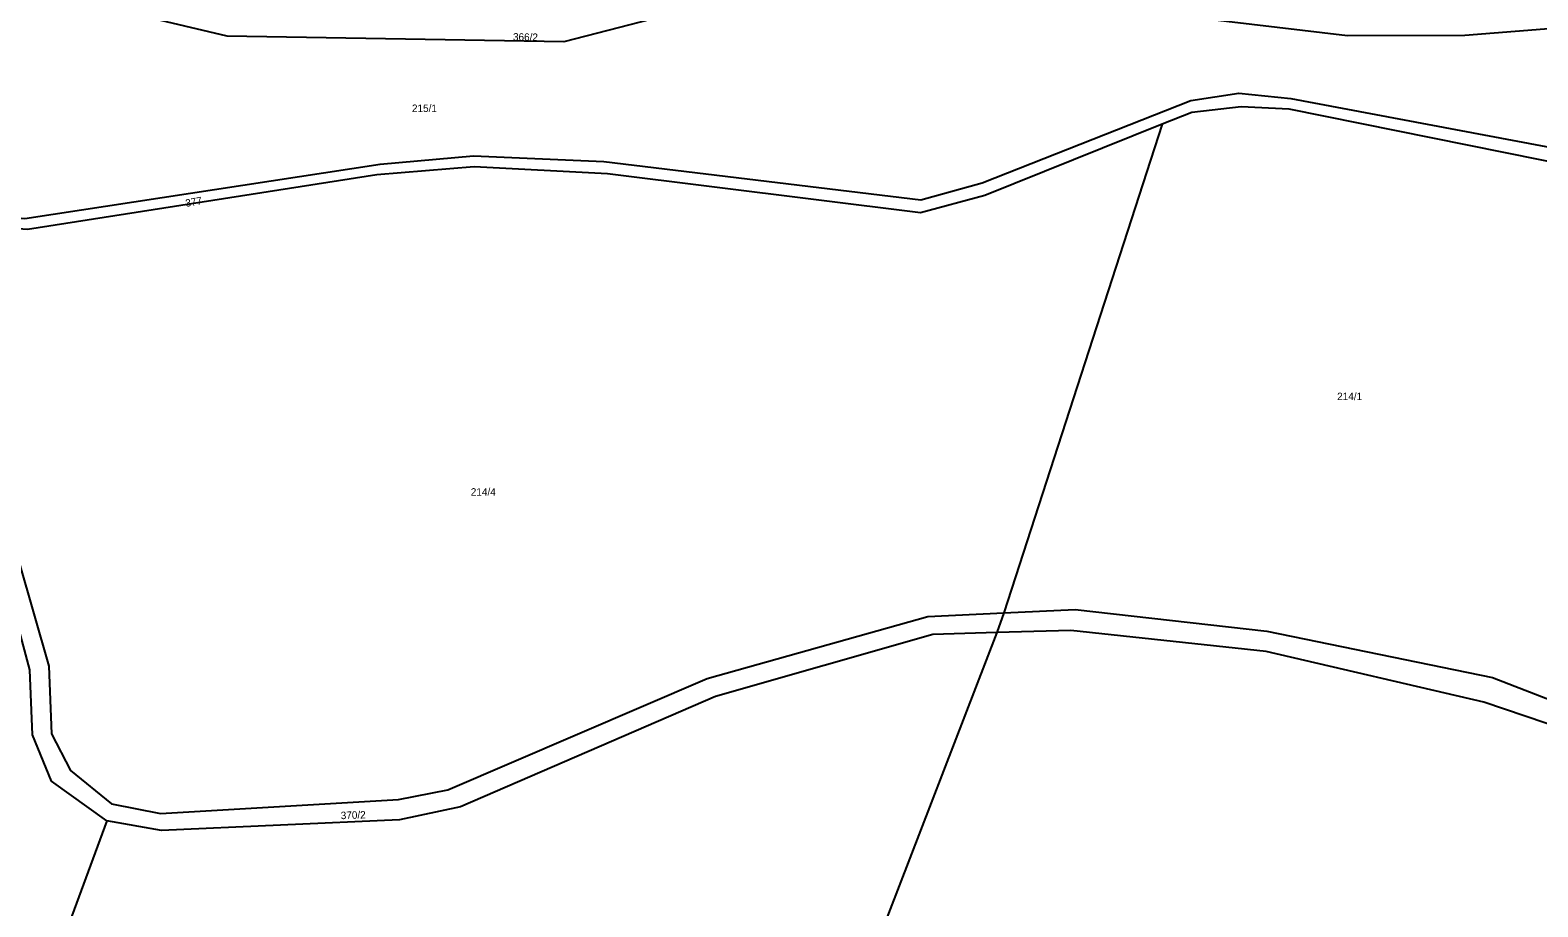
# Model space of a CAD drawing. Extents: x -880531 to -877616, y -1023932 to -1021350.
# Drawn here: x -878520.6 to -878177.4, y -1022709.3 to -1022509.8 of the extents above; entities that cross this region are included whole.
import ezdxf

# ---------------------------------------------------------------- set-up
doc = ezdxf.new("R2010")
doc.units = 0
doc.layers.add('Hranice parcel', color=7, linetype='Continuous')
doc.layers.add('Parcelní čísla', color=7, linetype='Continuous')

msp = doc.modelspace()

# ---------------------------------------------------------------- linework, layer by layer
at = {"layer": 'Hranice parcel'}
for p, q in [((-878262.91, -1022531.2), (-878298.99, -1022642.4)), ((-878298.99, -1022642.4), (-878300.59, -1022646.88)), ((-878300.59, -1022646.88), (-878347.85, -1022769.53)), ((-878503.14, -1022689.72), (-878513.6, -1022718.13))]:
    msp.add_line(p, q, dxfattribs=at)
for points in [[(-878125.35, -1022504.99), (-878146.35, -1022507.21), (-878194.02, -1022510.96), (-878220.76, -1022511.05), (-878280.27, -1022503.97), (-878335.4, -1022493.58), (-878344.86, -1022493.55), (-878371.73, -1022505.4), (-878399.1, -1022512.43), (-878475.7, -1022511.16), (-878508.77, -1022503.35), (-878545.47, -1022484.68), (-878615.6, -1022481.24), (-878635.5, -1022474.3), (-878648.14, -1022478.45), (-878668.08, -1022496.96), (-878691.68, -1022527.88), (-878708.19, -1022539.68), (-878731.2, -1022543.61), (-878748.07, -1022535.1), (-878763.51, -1022523.14)], [(-878772.34, -1022525.45), (-878758.55, -1022537.32), (-878734.74, -1022552.47), (-878725.11, -1022552.52), (-878697.59, -1022542.6), (-878692.56, -1022542.42), (-878672.91, -1022533.58), (-878660.33, -1022531.18), (-878648.04, -1022531.76), (-878616.24, -1022536.33), (-878607.61, -1022539.29), (-878559.76, -1022547.29), (-878533.18, -1022551.67), (-878521.77, -1022552.65), (-878440.9, -1022540.29), (-878419.64, -1022538.34), (-878389.99, -1022539.7), (-878317.85, -1022548.39), (-878303.92, -1022544.55), (-878256.37, -1022525.75), (-878245.48, -1022524.13), (-878233.68, -1022525.33), (-878151.01, -1022540.9)], [(-878152.5, -1022544.22), (-878234.05, -1022527.78), (-878244.93, -1022527.2), (-878256.18, -1022528.49), (-878262.91, -1022531.2)], [(-878262.91, -1022531.2), (-878303.25, -1022547.39), (-878317.9, -1022551.31), (-878389.14, -1022542.46), (-878419.52, -1022540.9), (-878441.69, -1022542.71), (-878521.19, -1022555.14), (-878532.17, -1022554.36), (-878559.74, -1022550.55), (-878604.26, -1022543.95)], [(-878604.26, -1022543.95), (-878579.05, -1022565.36), (-878555.67, -1022589.18), (-878536.69, -1022611.71), (-878523.17, -1022630.71), (-878516.35, -1022654.55), (-878515.73, -1022669.9), (-878511.39, -1022678.27), (-878502.03, -1022685.87), (-878490.91, -1022688.03), (-878436.73, -1022684.88), (-878425.48, -1022682.64), (-878366.49, -1022657.36), (-878316.24, -1022643.18), (-878298.99, -1022642.4)], [(-878503.14, -1022689.72), (-878515.73, -1022680.66), (-878520.02, -1022670.17), (-878520.65, -1022655.38), (-878526.53, -1022633.22)], [(-878298.99, -1022642.4), (-878282.71, -1022641.66), (-878239.13, -1022646.52), (-878187.76, -1022657.08), (-878174.22, -1022662.33)], [(-878300.59, -1022646.88), (-878315.09, -1022647.33), (-878364.57, -1022661.41), (-878422.59, -1022686.53), (-878436.49, -1022689.47), (-878490.65, -1022691.93), (-878503.14, -1022689.72)], [(-878018.01, -1022803.34), (-878064.23, -1022778.47), (-878092.6, -1022757.94), (-878107.19, -1022743.1), (-878120.43, -1022720.05), (-878128.98, -1022695.35), (-878138.59, -1022684.53), (-878153.41, -1022675.29), (-878175.6, -1022667.53), (-878189.73, -1022662.71), (-878239.29, -1022651.17), (-878283.75, -1022646.37), (-878300.59, -1022646.88)]]:
    msp.add_lwpolyline(points, dxfattribs=at)

# ---------------------------------------------------------------- texts
at = {"layer": 'Parcelní čísla'}
for s, rotation, p in [('366/2', 359, (-878410.694, -1022512.139)), ('377', 10, (-878485.072, -1022550.007)), ('370/2', 2, (-878449.85, -1022689.359))]:
    msp.add_text(s, height=1.7, rotation=rotation, dxfattribs=at).set_placement(p)
for s, p in [('215/1', (-878433.67, -1022528.4)), ('214/1', (-878223.1, -1022593.97)), ('214/4', (-878420.28, -1022615.72))]:
    msp.add_text(s, height=1.7, dxfattribs=at).set_placement(p)

doc.saveas('drawing.dxf')
